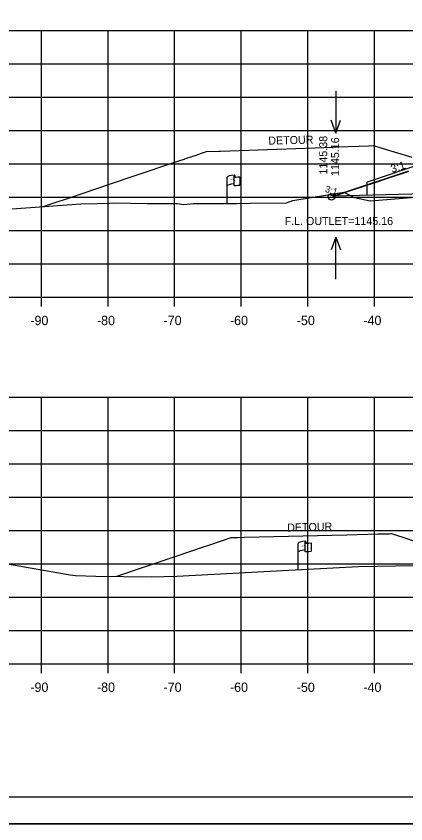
# Model space of a CAD drawing. Extents: x 1368971 to 1374497, y 378717 to 381839.
# Drawn here: x 1369549.1 to 1369607.6, y 378861.8 to 378982.9 of the extents above; entities that cross this region are included whole.
import ezdxf

# ---------------------------------------------------------------- set-up
doc = ezdxf.new("R2010")
doc.units = 0
for name, color, linetype in [('E_Existing ROW', 7, 'Continuous'), ('R_Axis', 7, 'Continuous'), ('R_Axis Annot', 7, 'Continuous'), ('R_Border', 7, 'Continuous'), ('R_Contours', 7, 'Continuous'), ('R_Exist Surface', 7, 'Continuous'), ('R_Fin Surface', 7, 'Continuous'), ('R_Grid', 7, 'Continuous'), ('R_No Plot', 7, 'Continuous'), ('R_Water', 7, 'Continuous'), ('R_Water Annot', 7, 'Continuous'), ('R_Xsect Elev', 7, 'Continuous'), ('R_Xsect Slope', 7, 'Continuous')]:
    doc.layers.add(name, color=color, linetype=linetype)

msp = doc.modelspace()

# ---------------------------------------------------------------- linework, layer by layer
at = {"layer": 'E_Existing ROW'}
for p, q in [((1369580.81, 378954.84), (1369580.81, 378958.79)), ((1369581.81, 378958.88), (1369581.81, 378958.87)), ((1369581.81, 378958.87), (1369581.81, 378957.64)), ((1369581.98, 378959.04), (1369581.98, 378958.8)), ((1369582.74, 378958.84), (1369582.74, 378957.6)), ((1369592.48, 378903.98), (1369592.48, 378903.96)), ((1369592.48, 378903.96), (1369592.48, 378902.74)), ((1369592.65, 378904.13), (1369592.65, 378903.89)), ((1369593.42, 378903.94), (1369593.42, 378902.7)), ((1369591.48, 378899.93), (1369591.48, 378903.88))]:
    msp.add_line(p, q, dxfattribs=at)
for centre, radius, start, end in [((1369581.89, 378958.88), 0.078, 88.6458, 274.2828), ((1369581.9, 378959.04), 0.0783, 263.0712, 93.9564), ((1369581.89, 378957.64), 0.0783, 180, 273.9564), ((1369592.56, 378903.98), 0.078, 88.6458, 274.2828), ((1369592.57, 378904.13), 0.0783, 263.0712, 93.9564), ((1369592.56, 378902.74), 0.0783, 180, 273.9564)]:
    msp.add_arc(centre, radius, start, end, dxfattribs=at)
for centre, major_axis, ratio, start_param, end_param in [((1369582.4, 378958.83), (-1.58, -0.04), 0.19887, 5.030368, 6.283185), ((1369583.1, 378958.95), (-1.23, -0.13), 0.052933, 0.159456, 1.268315), ((1369582.39, 378957.51), (-1.58, -0.04), 0.19887, 5.083035, 6.194897), ((1369583.1, 378957.71), (-1.23, -0.13), 0.052933, 0.159456, 1.268315), ((1369593.07, 378903.93), (-1.58, -0.04), 0.19887, 5.030368, 6.283185), ((1369593.77, 378904.04), (-1.23, -0.13), 0.052933, 0.159456, 1.268315), ((1369593.06, 378902.61), (-1.58, -0.04), 0.19887, 5.083035, 6.194897), ((1369593.77, 378902.8), (-1.23, -0.13), 0.052933, 0.159456, 1.268315)]:
    msp.add_ellipse(centre, major_axis=major_axis, ratio=ratio, start_param=start_param, end_param=end_param, dxfattribs=at)
at = {"layer": 'R_Axis'}
for p, q in [((1369502.93, 378940.81), (1369782.93, 378940.81)), ((1369552.93, 378939.41), (1369552.93, 378940.81)), ((1369562.93, 378939.41), (1369562.93, 378940.81)), ((1369572.93, 378939.41), (1369572.93, 378940.81)), ((1369582.93, 378939.41), (1369582.93, 378940.81)), ((1369592.93, 378939.41), (1369592.93, 378940.81)), ((1369602.93, 378939.41), (1369602.93, 378940.81)), ((1369502.93, 378885.81), (1369782.93, 378885.81)), ((1369552.93, 378884.41), (1369552.93, 378885.81)), ((1369562.93, 378884.41), (1369562.93, 378885.81)), ((1369572.93, 378884.41), (1369572.93, 378885.81)), ((1369582.93, 378884.41), (1369582.93, 378885.81)), ((1369592.93, 378884.41), (1369592.93, 378885.81)), ((1369602.93, 378884.41), (1369602.93, 378885.81))]:
    msp.add_line(p, q, dxfattribs=at)
at = {"layer": 'R_Border'}
msp.add_line((1369801.11, 378865.81), (1369484.93, 378865.81), dxfattribs=at)
at = {"layer": 'R_Contours'}
msp.add_lwpolyline([(1369608.05, 378959.71), (1369604.29, 378958.46), (1369602.27, 378957.79), (1369601.89, 378957.66), (1369601.22, 378957.44), (1369599.42, 378956.84), (1369598.43, 378956.51), (1369599.94, 378955.73), (1369602.31, 378955.27), (1369610.34, 378955.89)], dxfattribs=at)
msp.add_lwpolyline([(1369596.8, 378955.97), (1369596.8, 378956.31), (1369598.32, 378956.56), (1369598.43, 378956.51), (1369598.18, 378956.42)], close=True, dxfattribs=at)
at = {"layer": 'R_Exist Surface'}
for points in [[(1369548.56, 378954.05), (1369558.84, 378954.81), (1369561.28, 378954.86), (1369563.21, 378954.89), (1369563.82, 378954.96), (1369568.79, 378954.86), (1369573.3, 378954.85), (1369574.32, 378954.72), (1369575.74, 378954.85), (1369582.26, 378954.83), (1369584.31, 378954.91), (1369589.73, 378954.93), (1369590.67, 378955.29), (1369598.32, 378956.56), (1369599.94, 378955.73), (1369602.31, 378955.27), (1369610.34, 378955.89)], [(1369539.76, 378902.21), (1369557.26, 378899.16), (1369558.04, 378899.05), (1369561.11, 378898.95), (1369569.47, 378898.84), (1369573.24, 378898.97), (1369590.09, 378899.86), (1369600.56, 378900.4), (1369608.88, 378900.55)]]:
    msp.add_lwpolyline(points, dxfattribs=at)
at = {"layer": 'R_Fin Surface'}
msp.add_line((1369596.8, 378955.97), (1369596.09, 378956.19), dxfattribs=at)
for points in [[(1369553.21, 378954.4), (1369553.35, 378954.44), (1369553.4, 378954.46), (1369553.52, 378954.5), (1369553.65, 378954.54), (1369554.1, 378954.7), (1369557.74, 378955.92), (1369558.9, 378956.31), (1369559.34, 378956.46), (1369560.96, 378957), (1369566.41, 378958.83), (1369573.56, 378961.23), (1369574.38, 378961.5), (1369574.4, 378961.51), (1369574.47, 378961.53), (1369574.73, 378961.62), (1369575.64, 378961.93), (1369576.18, 378962.11), (1369576.96, 378962.37), (1369577.72, 378962.63), (1369579.59, 378962.69), (1369579.78, 378962.7), (1369579.8, 378962.7), (1369588.28, 378963), (1369593.98, 378963.21), (1369596.69, 378963.31), (1369597.34, 378963.33), (1369600.66, 378963.45), (1369602.09, 378963.51), (1369602.75, 378963.53), (1369604.07, 378963.13), (1369605.7, 378962.64), (1369605.78, 378962.62), (1369605.88, 378962.59), (1369608.52, 378961.79)], [(1369596.8, 378955.97), (1369598.18, 378956.42), (1369599.42, 378956.84), (1369601.22, 378957.44), (1369601.89, 378957.66), (1369602.27, 378957.79), (1369604.29, 378958.46), (1369608.05, 378959.71)], [(1369596.93, 378955.98), (1369598.31, 378956.43), (1369599.18, 378956.73), (1369600.43, 378957.14), (1369600.94, 378957.31), (1369601.91, 378957.63), (1369602.28, 378957.76), (1369605.37, 378958.79), (1369607.55, 378959.52), (1369608.1, 378959.7)], [(1369564.24, 378898.96), (1369573.02, 378901.92), (1369577.41, 378903.4), (1369577.76, 378903.51), (1369578.22, 378903.67), (1369579.96, 378904.26), (1369581.42, 378904.75), (1369582.43, 378904.77), (1369583.43, 378904.8), (1369598.81, 378905.18), (1369603.47, 378905.29), (1369605.21, 378905.33), (1369605.48, 378905.34), (1369608.08, 378904.49), (1369608.31, 378904.41), (1369608.33, 378904.41), (1369608.48, 378904.36), (1369612.89, 378902.91), (1369617.2, 378901.5)]]:
    msp.add_lwpolyline(points, dxfattribs=at)
at = {"layer": 'R_Grid'}
for p, q in [((1369502.93, 378980.81), (1369782.93, 378980.81)), ((1369552.93, 378940.81), (1369552.93, 378980.81)), ((1369562.93, 378940.81), (1369562.93, 378980.81)), ((1369572.93, 378940.81), (1369572.93, 378980.81)), ((1369582.93, 378940.81), (1369582.93, 378980.81)), ((1369592.93, 378940.81), (1369592.93, 378980.81)), ((1369602.93, 378940.81), (1369602.93, 378980.81)), ((1369502.93, 378975.81), (1369782.93, 378975.81)), ((1369502.93, 378970.81), (1369782.93, 378970.81)), ((1369502.93, 378965.81), (1369782.93, 378965.81)), ((1369502.93, 378960.81), (1369782.93, 378960.81)), ((1369502.93, 378955.81), (1369782.93, 378955.81)), ((1369502.93, 378950.81), (1369782.93, 378950.81)), ((1369502.93, 378945.81), (1369782.93, 378945.81)), ((1369502.93, 378940.81), (1369782.93, 378940.81)), ((1369502.93, 378925.81), (1369782.93, 378925.81)), ((1369552.93, 378885.81), (1369552.93, 378925.81)), ((1369562.93, 378885.81), (1369562.93, 378925.81)), ((1369572.93, 378885.81), (1369572.93, 378925.81)), ((1369582.93, 378885.81), (1369582.93, 378925.81)), ((1369592.93, 378885.81), (1369592.93, 378925.81)), ((1369602.93, 378885.81), (1369602.93, 378925.81)), ((1369502.93, 378920.81), (1369782.93, 378920.81)), ((1369502.93, 378915.81), (1369782.93, 378915.81)), ((1369502.93, 378910.81), (1369782.93, 378910.81)), ((1369502.93, 378905.81), (1369782.93, 378905.81)), ((1369502.93, 378900.81), (1369782.93, 378900.81)), ((1369502.93, 378895.81), (1369782.93, 378895.81)), ((1369502.93, 378890.81), (1369782.93, 378890.81)), ((1369502.93, 378885.81), (1369782.93, 378885.81))]:
    msp.add_line(p, q, dxfattribs=at)
at = {"layer": 'R_No Plot'}
msp.add_line((1369472.53, 378861.83), (1369805.86, 378861.83), dxfattribs=at)
for points in [[(1369472.52, 379075.16), (1369805.86, 379075.16), (1369805.86, 378861.82), (1369472.52, 378861.82)], [(1369718.85, 379071.27), (1369718.85, 379061.39), (1369754.58, 379061.39), (1369754.58, 379058.47), (1369777.78, 379058.47), (1369777.78, 379035.25), (1369801.11, 379035.25), (1369801.11, 378865.81), (1369484.93, 378865.81), (1369484.93, 379071.27)]]:
    msp.add_lwpolyline(points, close=True, dxfattribs=at)
msp.add_circle((1369596.5, 378955.86), 0.5, dxfattribs=at)
at = {"layer": 'R_Water'}
for p, q in [((1369610.77, 378961.04), (1369601.84, 378958.06)), ((1369601.84, 378956.08), (1369601.84, 378958.06)), ((1369610.77, 378956.28), (1369596.8, 378955.97))]:
    msp.add_line(p, q, dxfattribs=at)
at = {"layer": 'R_Water Annot'}
for p, q in [((1369597.13, 378971.68), (1369597.13, 378965.39)), ((1369597.13, 378965.39), (1369596.43, 378967.32)), ((1369597.13, 378965.39), (1369597.83, 378967.32)), ((1369597.13, 378949.8), (1369596.43, 378947.88)), ((1369597.13, 378943.52), (1369597.13, 378949.8)), ((1369597.13, 378949.8), (1369597.83, 378947.88))]:
    msp.add_line(p, q, dxfattribs=at)

# ---------------------------------------------------------------- texts
at = {"layer": 'E_Existing ROW'}
for s, height, rotation, p in [('R ', 0.2, 9.9884, (1369581.33, 378958.29)), (' O', 0.2, 9.9884, (1369581.48, 378958.33)), ('DWB 11-9-07', 0.001, 90, (1369581.98, 378958.8)), ('W', 0.2, 351.1788, (1369581.81, 378958.16)), ('DWB 11-9-07', 0.001, 5.0717, (1369582.73, 378957.6)), ('DWB 11-9-07', 0.001, 90, (1369580.81, 378954.84)), ('R ', 0.2, 9.9884, (1369592, 378903.38)), (' O', 0.2, 9.9884, (1369592.15, 378903.43)), ('W', 0.2, 351.1788, (1369592.48, 378903.26)), ('DWB 11-9-07', 0.001, 90, (1369592.65, 378903.89)), ('DWB 11-9-07', 0.001, 5.0717, (1369593.4, 378902.7)), ('DWB 11-9-07', 0.001, 90, (1369591.48, 378899.93))]:
    msp.add_text(s, height=height, rotation=rotation, dxfattribs=at).set_placement(p)
at = {"layer": 'R_Axis Annot'}
for s, p in [('-90', (1369551.27, 378936.61)), ('-80', (1369561.27, 378936.61)), ('-70', (1369571.27, 378936.61)), ('-60', (1369581.24, 378936.61)), ('-50', (1369591.27, 378936.61)), ('-40', (1369601.27, 378936.61)), ('-90', (1369551.27, 378881.61)), ('-80', (1369561.27, 378881.61)), ('-70', (1369571.27, 378881.61)), ('-60', (1369581.24, 378881.61)), ('-50', (1369591.27, 378881.61)), ('-40', (1369601.27, 378881.61))]:
    msp.add_text(s, height=1.4, dxfattribs=at).set_placement(p)
at = {"layer": 'R_Water Annot'}
for p in [(1369587.01, 378963.67), (1369589.84, 378905.65)]:
    msp.add_text('DETOUR', height=1.2, rotation=1.4118, dxfattribs=at).set_placement(p)
msp.add_text('F.L. OUTLET=1145.16', height=1.2, dxfattribs=at).set_placement((1369589.45, 378951.62))
at = {"layer": 'R_Xsect Elev'}
for s, p in [('1145.38', (1369595.84, 378959.19)), ('1145.16', (1369597.62, 378958.97))]:
    msp.add_text(s, height=1.2, rotation=90, dxfattribs=at).set_placement(p)
at = {"layer": 'R_Xsect Slope'}
for height, rotation, p in [(1.2, 18.4213, (1369605.58, 378959.42)), (1, 342.7305, (1369595.44, 378956.61))]:
    msp.add_text('3:1', height=height, rotation=rotation, dxfattribs=at).set_placement(p)

doc.saveas('drawing.dxf')
